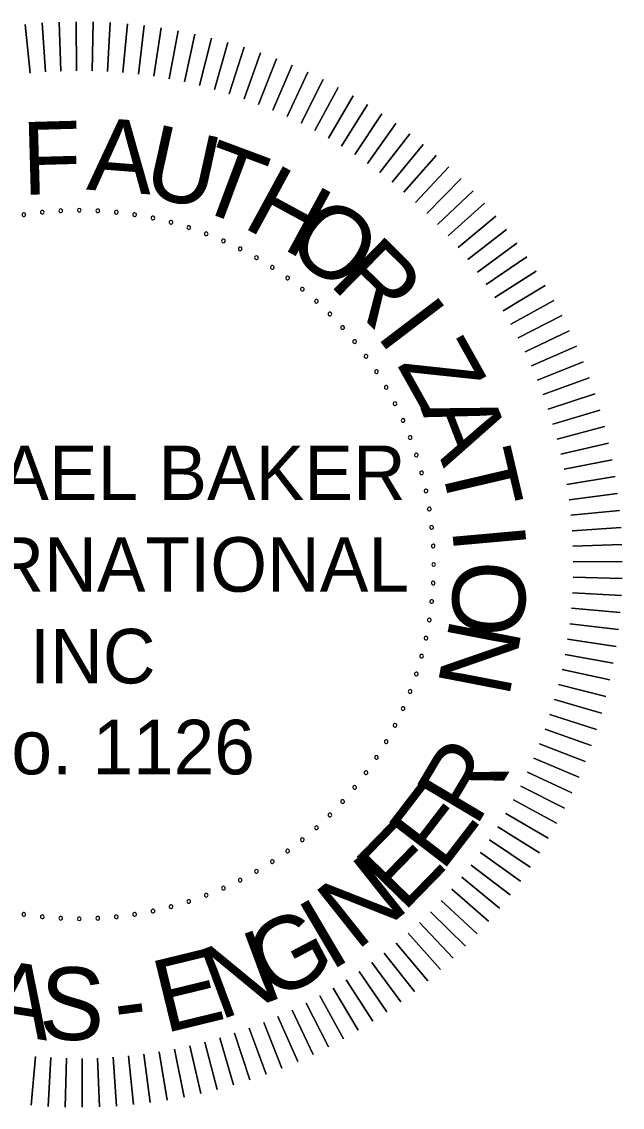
# Model space of a CAD drawing. Extents: x 166 to 3995, y -61 to 2074.
# Drawn here: x 3062.3 to 3204.5, y 406.5 to 663.7 of the extents above; entities that cross this region are included whole.
import ezdxf

# ---------------------------------------------------------------- set-up
doc = ezdxf.new("R2010")
doc.units = 0
doc.layers.add('G-ANNO-TEXT', color=7, linetype='Continuous')

msp = doc.modelspace()

# ---------------------------------------------------------------- linework, layer by layer
at = {"layer": 'G-ANNO-TEXT'}
for points in [[(3075.26, 652.09), (3075.19, 663.69)], [(3075.19, 663.69), (3075.26, 652.09)], [(3064.25, 651.51), (3063.09, 663.05)], [(3063.09, 663.05), (3064.25, 651.51)], [(3067.91, 651.82), (3067.12, 663.39)], [(3067.12, 663.39), (3067.91, 651.82)], [(3071.58, 652.01), (3071.15, 663.61)], [(3071.15, 663.61), (3071.58, 652.01)], [(3078.93, 652.05), (3079.23, 663.65)], [(3079.23, 663.65), (3078.93, 652.05)], [(3082.61, 651.9), (3083.27, 663.48)], [(3083.27, 663.48), (3082.61, 651.9)], [(3086.27, 651.63), (3087.3, 663.19)], [(3087.3, 663.19), (3086.27, 651.63)], [(3089.93, 651.25), (3091.32, 662.77)], [(3091.32, 662.77), (3089.93, 651.25)], [(3093.57, 650.75), (3095.32, 662.22)], [(3095.32, 662.22), (3093.57, 650.75)], [(3097.2, 650.14), (3099.31, 661.55)], [(3099.31, 661.55), (3097.2, 650.14)], [(3100.8, 649.42), (3103.27, 660.75)], [(3103.27, 660.75), (3100.8, 649.42)], [(3104.38, 648.58), (3107.2, 659.83)], [(3107.2, 659.83), (3104.38, 648.58)], [(3107.93, 647.63), (3111.11, 658.78)], [(3111.11, 658.78), (3107.93, 647.63)], [(3111.45, 646.57), (3114.97, 657.62)], [(3114.97, 657.62), (3111.45, 646.57)], [(3114.94, 645.39), (3118.8, 656.33)], [(3118.8, 656.33), (3114.94, 645.39)], [(3118.38, 644.11), (3122.59, 654.92)], [(3122.59, 654.92), (3118.38, 644.11)], [(3121.79, 642.73), (3126.33, 653.4)], [(3126.33, 653.4), (3121.79, 642.73)], [(3125.15, 641.23), (3130.03, 651.76)], [(3130.03, 651.76), (3125.15, 641.23)], [(3128.46, 639.63), (3133.66, 650)], [(3133.66, 650), (3128.46, 639.63)], [(3131.71, 637.93), (3137.25, 648.13)], [(3137.25, 648.13), (3131.71, 637.93)], [(3134.92, 636.13), (3140.77, 646.14)], [(3140.77, 646.14), (3134.92, 636.13)], [(3138.06, 634.22), (3144.22, 644.05)], [(3144.22, 644.05), (3138.06, 634.22)], [(3141.15, 632.22), (3147.61, 641.85)], [(3147.61, 641.85), (3141.15, 632.22)], [(3144.17, 630.13), (3150.93, 639.55)], [(3150.93, 639.55), (3144.17, 630.13)], [(3147.12, 627.94), (3154.18, 637.14)], [(3154.18, 637.14), (3147.12, 627.94)], [(3150, 625.65), (3157.34, 634.63)], [(3157.34, 634.63), (3150, 625.65)], [(3152.81, 623.28), (3160.43, 632.02)], [(3160.43, 632.02), (3152.81, 623.28)], [(3163.43, 629.32), (3155.54, 620.82)], [(3155.54, 620.82), (3163.43, 629.32)], [(3166.35, 626.53), (3158.2, 618.28)], [(3158.2, 618.28), (3166.35, 626.53)], [(3169.18, 623.64), (3160.77, 615.65)], [(3160.77, 615.65), (3169.18, 623.64)], [(3171.92, 620.67), (3163.26, 612.95)], [(3163.26, 612.95), (3171.92, 620.67)], [(3174.56, 617.61), (3165.66, 610.17)], [(3165.66, 610.17), (3174.56, 617.61)], [(3177.1, 614.47), (3167.98, 607.31)], [(3167.98, 607.31), (3177.1, 614.47)], [(3179.54, 611.25), (3170.2, 604.38)], [(3170.2, 604.38), (3179.54, 611.25)], [(3181.89, 607.96), (3172.33, 601.39)], [(3172.33, 601.39), (3181.89, 607.96)], [(3184.12, 604.59), (3174.36, 598.32)], [(3174.36, 598.32), (3184.12, 604.59)], [(3186.25, 601.16), (3176.3, 595.2)], [(3176.3, 595.2), (3186.25, 601.16)], [(3188.28, 597.66), (3178.14, 592.02)], [(3178.14, 592.02), (3188.28, 597.66)], [(3190.19, 594.1), (3179.88, 588.78)], [(3179.88, 588.78), (3190.19, 594.1)], [(3191.98, 590.48), (3181.52, 585.49)], [(3181.52, 585.49), (3191.98, 590.48)], [(3193.67, 586.81), (3183.05, 582.14)], [(3183.05, 582.14), (3193.67, 586.81)], [(3195.23, 583.09), (3184.47, 578.76)], [(3184.47, 578.76), (3195.23, 583.09)], [(3196.68, 579.31), (3185.79, 575.32)], [(3185.79, 575.32), (3196.68, 579.31)], [(3198.01, 575.5), (3187, 571.85)], [(3187, 571.85), (3198.01, 575.5)], [(3199.22, 571.64), (3188.1, 568.35)], [(3188.1, 568.35), (3199.22, 571.64)], [(3200.31, 567.75), (3189.09, 564.81)], [(3189.09, 564.81), (3200.31, 567.75)], [(3201.28, 563.83), (3189.97, 561.24)], [(3189.97, 561.24), (3201.28, 563.83)], [(3202.12, 559.88), (3190.74, 557.64)], [(3190.74, 557.64), (3202.12, 559.88)], [(3202.83, 555.9), (3191.39, 554.02)], [(3191.39, 554.02), (3202.83, 555.9)], [(3203.43, 551.9), (3191.93, 550.39)], [(3191.93, 550.39), (3203.43, 551.9)], [(3203.89, 547.89), (3192.35, 546.73)], [(3192.35, 546.73), (3203.89, 547.89)], [(3204.23, 543.86), (3192.66, 543.07)], [(3192.66, 543.07), (3204.23, 543.86)], [(3204.44, 539.83), (3192.85, 539.4)], [(3192.85, 539.4), (3204.44, 539.83)], [(3204.53, 535.79), (3192.93, 535.72)], [(3192.93, 535.72), (3204.53, 535.79)], [(3204.49, 531.75), (3192.89, 532.05)], [(3192.89, 532.05), (3204.49, 531.75)], [(3204.32, 527.71), (3192.74, 528.37)], [(3192.74, 528.37), (3204.32, 527.71)], [(3204.03, 523.68), (3192.47, 524.71)], [(3192.47, 524.71), (3204.03, 523.68)], [(3203.61, 519.66), (3192.09, 521.05)], [(3192.09, 521.05), (3203.61, 519.66)], [(3203.06, 515.66), (3191.59, 517.41)], [(3191.59, 517.41), (3203.06, 515.66)], [(3202.39, 511.67), (3190.98, 513.78)], [(3190.98, 513.78), (3202.39, 511.67)], [(3201.59, 507.71), (3190.26, 510.18)], [(3190.26, 510.18), (3201.59, 507.71)], [(3200.67, 503.78), (3189.42, 506.6)], [(3189.42, 506.6), (3200.67, 503.78)], [(3199.62, 499.88), (3188.47, 503.05)], [(3188.47, 503.05), (3199.62, 499.88)], [(3198.46, 496.01), (3187.41, 499.53)], [(3187.41, 499.53), (3198.46, 496.01)], [(3197.17, 492.18), (3186.23, 496.05)], [(3186.23, 496.05), (3197.17, 492.18)], [(3195.76, 488.39), (3184.95, 492.6)], [(3184.95, 492.6), (3195.76, 488.39)], [(3194.24, 484.65), (3183.57, 489.2)], [(3183.57, 489.2), (3194.24, 484.65)], [(3192.59, 480.96), (3182.07, 485.84)], [(3182.07, 485.84), (3192.59, 480.96)], [(3190.84, 477.32), (3180.47, 482.53)], [(3180.47, 482.53), (3190.84, 477.32)], [(3188.97, 473.74), (3178.77, 479.27)], [(3178.77, 479.27), (3188.97, 473.74)], [(3186.98, 470.22), (3176.97, 476.06)], [(3176.97, 476.06), (3186.98, 470.22)], [(3184.89, 466.76), (3175.06, 472.92)], [(3175.06, 472.92), (3184.89, 466.76)], [(3182.69, 463.37), (3173.06, 469.84)], [(3173.06, 469.84), (3182.69, 463.37)], [(3180.39, 460.05), (3170.97, 466.82)], [(3170.97, 466.82), (3180.39, 460.05)], [(3177.98, 456.81), (3168.77, 463.86)], [(3168.77, 463.86), (3177.98, 456.81)], [(3175.47, 453.64), (3166.49, 460.98)], [(3166.49, 460.98), (3175.47, 453.64)], [(3172.86, 450.55), (3164.12, 458.17)], [(3164.12, 458.17), (3172.86, 450.55)], [(3170.16, 447.55), (3161.66, 455.44)], [(3161.66, 455.44), (3170.16, 447.55)], [(3167.37, 444.63), (3159.12, 452.79)], [(3159.12, 452.79), (3167.37, 444.63)], [(3164.48, 441.8), (3156.49, 450.21)], [(3156.49, 450.21), (3164.48, 441.8)], [(3161.51, 439.07), (3153.79, 447.72)], [(3153.79, 447.72), (3161.51, 439.07)], [(3158.45, 436.43), (3151, 445.32)], [(3151, 445.32), (3158.45, 436.43)], [(3155.31, 433.88), (3148.15, 443.01)], [(3148.15, 443.01), (3155.31, 433.88)], [(3152.09, 431.44), (3145.22, 440.78)], [(3145.22, 440.78), (3152.09, 431.44)], [(3148.8, 429.1), (3142.23, 438.65)], [(3142.23, 438.65), (3148.8, 429.1)], [(3145.43, 426.86), (3139.16, 436.62)], [(3139.16, 436.62), (3145.43, 426.86)], [(3138.5, 422.71), (3132.86, 432.84)], [(3132.86, 432.84), (3138.5, 422.71)], [(3142, 424.73), (3136.04, 434.68)], [(3136.04, 434.68), (3142, 424.73)], [(3134.94, 420.8), (3129.62, 431.1)], [(3129.62, 431.1), (3134.94, 420.8)], [(3127.65, 417.31), (3122.98, 427.93)], [(3122.98, 427.93), (3127.65, 417.31)], [(3131.32, 419), (3126.33, 429.47)], [(3126.33, 429.47), (3131.32, 419)], [(3120.15, 414.3), (3116.16, 425.19)], [(3116.16, 425.19), (3120.15, 414.3)], [(3123.93, 415.75), (3119.6, 426.51)], [(3119.6, 426.51), (3123.93, 415.75)], [(3108.59, 410.67), (3105.64, 421.89)], [(3105.64, 421.89), (3108.59, 410.67)], [(3112.48, 411.76), (3109.18, 422.88)], [(3109.18, 422.88), (3112.48, 411.76)], [(3116.34, 412.97), (3112.69, 423.98)], [(3112.69, 423.98), (3116.34, 412.97)], [(3096.74, 408.15), (3094.86, 419.59)], [(3094.86, 419.59), (3096.74, 408.15)], [(3100.72, 408.86), (3098.48, 420.25)], [(3098.48, 420.25), (3100.72, 408.86)], [(3104.67, 409.71), (3102.07, 421.01)], [(3102.07, 421.01), (3104.67, 409.71)], [(3064.52, 406.96), (3065.55, 418.51)], [(3065.55, 418.51), (3064.52, 406.96)], [(3068.55, 406.66), (3069.21, 418.24)], [(3069.21, 418.24), (3068.55, 406.66)], [(3072.59, 406.49), (3072.89, 418.09)], [(3072.89, 418.09), (3072.59, 406.49)], [(3076.63, 406.45), (3076.56, 418.05)], [(3076.56, 418.05), (3076.63, 406.45)], [(3080.67, 406.54), (3080.24, 418.13)], [(3080.24, 418.13), (3080.67, 406.54)], [(3084.7, 406.75), (3083.91, 418.32)], [(3083.91, 418.32), (3084.7, 406.75)], [(3088.73, 407.09), (3087.57, 418.63)], [(3087.57, 418.63), (3088.73, 407.09)], [(3092.74, 407.56), (3091.22, 419.06)], [(3091.22, 419.06), (3092.74, 407.56)]]:
    msp.add_lwpolyline(points, dxfattribs=at)
for centre, start, end in [((3062.78, 617.98), 9, 189), ((3062.78, 617.98), 189, 9), ((3067.14, 618.55), 6, 186), ((3067.14, 618.55), 186, 6), ((3071.52, 618.9), 3, 183), ((3071.52, 618.9), 183, 3), ((3075.91, 619.01), 0, 180), ((3075.91, 619.01), 180, 0), ((3080.3, 618.9), 357, 177), ((3080.3, 618.9), 177, 357), ((3084.69, 618.55), 174, 354), ((3084.69, 618.55), 354, 174), ((3089.04, 617.98), 171, 351), ((3089.04, 617.98), 351, 171), ((3093.36, 617.18), 348, 168), ((3093.36, 617.18), 168, 348), ((3097.64, 616.15), 165, 345), ((3097.64, 616.15), 345, 165), ((3101.85, 614.91), 162, 342), ((3101.85, 614.91), 342, 162), ((3105.99, 613.44), 159, 339), ((3105.99, 613.44), 339, 159), ((3110.05, 611.76), 156, 336), ((3110.05, 611.76), 336, 156), ((3114.02, 609.87), 153, 333), ((3114.02, 609.87), 333, 153), ((3117.88, 607.77), 150, 330), ((3117.88, 607.77), 330, 150), ((3121.63, 605.47), 147, 327), ((3121.63, 605.47), 327, 147), ((3125.25, 602.98), 144, 324), ((3125.25, 602.98), 324, 144), ((3128.74, 600.31), 141, 321), ((3128.74, 600.31), 321, 141), ((3132.08, 597.45), 138, 318), ((3132.08, 597.45), 318, 138), ((3135.27, 594.43), 135, 315), ((3135.27, 594.43), 315, 135), ((3138.29, 591.24), 312, 132), ((3138.29, 591.24), 132, 312), ((3141.15, 587.9), 129, 309), ((3141.15, 587.9), 309, 129), ((3143.82, 584.41), 126, 306), ((3143.82, 584.41), 306, 126), ((3146.31, 580.79), 123, 303), ((3146.31, 580.79), 303, 123), ((3148.61, 577.04), 120, 300), ((3148.61, 577.04), 300, 120), ((3150.7, 573.18), 117, 297), ((3150.7, 573.18), 297, 117), ((3152.6, 569.21), 114, 294), ((3152.6, 569.21), 294, 114), ((3154.28, 565.15), 111, 291), ((3154.28, 565.15), 291, 111), ((3155.75, 561.01), 108, 288), ((3155.75, 561.01), 288, 108), ((3156.99, 556.8), 105, 285), ((3156.99, 556.8), 285, 105), ((3158.02, 552.52), 102, 282), ((3158.02, 552.52), 282, 102), ((3158.82, 548.2), 99, 279), ((3158.82, 548.2), 279, 99), ((3159.39, 543.85), 96, 276), ((3159.39, 543.85), 276, 96), ((3159.74, 539.46), 93, 273), ((3159.74, 539.46), 273, 93), ((3159.85, 535.07), 90, 270), ((3159.85, 535.07), 270, 90), ((3159.74, 530.68), 87, 267), ((3159.74, 530.68), 267, 87), ((3159.39, 526.3), 84, 264), ((3159.39, 526.3), 264, 84), ((3158.82, 521.94), 81, 261), ((3158.82, 521.94), 261, 81), ((3158.02, 517.62), 78, 258), ((3158.02, 517.62), 258, 78), ((3156.99, 513.35), 75, 255), ((3156.99, 513.35), 255, 75), ((3155.75, 509.13), 72, 252), ((3155.75, 509.13), 252, 72), ((3154.28, 504.99), 69, 249), ((3154.28, 504.99), 249, 69), ((3152.6, 500.93), 66, 246), ((3152.6, 500.93), 246, 66), ((3150.7, 496.96), 63, 243), ((3150.7, 496.96), 243, 63), ((3148.61, 493.1), 60, 240), ((3148.61, 493.1), 240, 60), ((3146.31, 489.35), 57, 237), ((3146.31, 489.35), 237, 57), ((3143.82, 485.73), 54, 234), ((3143.82, 485.73), 234, 54), ((3141.15, 482.24), 51, 231), ((3141.15, 482.24), 231, 51), ((3138.29, 478.9), 48, 228), ((3138.29, 478.9), 228, 48), ((3135.27, 475.71), 45, 225), ((3135.27, 475.71), 225, 45), ((3132.08, 472.69), 42, 222), ((3132.08, 472.69), 222, 42), ((3128.74, 469.84), 39, 219), ((3128.74, 469.84), 219, 39), ((3125.25, 467.16), 36, 216), ((3125.25, 467.16), 216, 36), ((3121.63, 464.67), 33, 213), ((3121.63, 464.67), 213, 33), ((3114.02, 460.28), 27, 207), ((3114.02, 460.28), 207, 27), ((3117.88, 462.37), 30, 210), ((3117.88, 462.37), 210, 30), ((3110.05, 458.39), 24, 204), ((3110.05, 458.39), 204, 24), ((3101.85, 455.24), 18, 198), ((3101.85, 455.24), 198, 18), ((3105.99, 456.7), 21, 201), ((3105.99, 456.7), 201, 21), ((3093.36, 452.96), 12, 192), ((3093.36, 452.96), 192, 12), ((3097.64, 453.99), 15, 195), ((3097.64, 453.99), 195, 15), ((3062.78, 452.16), 351, 171), ((3062.78, 452.16), 171, 351), ((3067.14, 451.59), 354, 174), ((3067.14, 451.59), 174, 354), ((3071.52, 451.24), 357, 177), ((3071.52, 451.24), 177, 357), ((3075.91, 451.13), 0, 180), ((3075.91, 451.13), 180, 0), ((3080.3, 451.24), 3, 183), ((3080.3, 451.24), 183, 3), ((3084.69, 451.59), 6, 186), ((3084.69, 451.59), 186, 6), ((3089.04, 452.16), 9, 189), ((3089.04, 452.16), 189, 9)]:
    msp.add_arc(centre, 0.431, start, end, dxfattribs=at)

# ---------------------------------------------------------------- texts
for s, rotation, p in [('A', 355.5955, (3077.48, 623.92)), ('F', 1.5867, (3062.54, 622.65)), ('U', 347.5481, (3090.51, 622.69)), ('T', 339.5007, (3102.54, 619.81)), ('H', 331.4533, (3114.22, 615.21)), ('O', 323.4059, (3124.11, 609.76)), ('R', 315.3585, (3134.79, 601.59)), ('I', 307.3112, (3145.99, 589.46)), ('Z', 299.2638, (3151.05, 582.44)), ('A', 291.2164, (3156.7, 572.08)), ('T', 283.169, (3161.2, 559.89)), ('I', 275.1216, (3164.19, 543.76)), ('O', 267.0743, (3164.79, 536.36)), ('N', 259.0269, (3163.89, 522.82)), ('R', 59.2262, (3169.83, 472.6)), ('E', 52.4765, (3161.84, 462)), ('E', 45.7268, (3152.65, 452.4)), ('N', 38.4196, (3141.51, 443.31)), ('I', 30.5495, (3135.26, 438.57)), ('G', 27.7404, (3121.64, 431.34)), ('N', 20.4332, (3109.1, 426.99)), ('E', 13.6835, (3096.11, 423.95)), ('A', 351.1991, (3053.12, 424.6)), ('S', 357.9489, (3066.26, 422.69)), ('-', 7.5077, (3085.06, 422.65))]:
    msp.add_text(s, height=17.23, rotation=rotation, dxfattribs=at).set_placement(p)
for s, height, p in [('MICHAEL BAKER', 12.9215, (3013.04, 550.34)), (' INTERNATIONAL', 12.9215, (3010.96, 528.62)), ('INC', 12.922, (3064.21, 506.89)), (' No. 1126', 12.922, (3042.56, 485.35))]:
    msp.add_text(s, height=height, dxfattribs=at).set_placement(p)

doc.saveas('drawing.dxf')
